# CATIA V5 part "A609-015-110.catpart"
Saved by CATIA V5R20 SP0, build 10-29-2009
Part number: A609-015-110
Source: Unknown
Property "ARTICLENO": "A609-015-110"
Property "B": "12.500"
Property "BOMINFO": "A609-015-110"
Property "CODE": "A609-015-110"
Property "D": "18.000"
Property "D1": "11.000"
Property "FORM": "A"
Property "L": "110.000"
Property "L1": "25.000"
Property "L2": "60.000"
Property "LINA": "A609-015-110"
Property "NB": "A609-015-110"
Property "NBSYN": "$CODE."
Property "NN": "A609"
Property "NT": "VDI 3357 E-Type Wear Plates, self-lubricating"
Property "S": "15.000"
Property "SUPPLIER": "CF"
Property "T": "10.500"
Property "W": "25.000"
Bounding box of the stored display mesh (mm): x 0 to 110, y 0 to 15, z 0 to 25
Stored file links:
  C:\Users\Utente\Desktop\3D files A609\A609-015-110.catpart
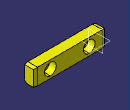
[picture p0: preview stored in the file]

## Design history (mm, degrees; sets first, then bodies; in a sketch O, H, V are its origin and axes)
Body1 "Geometry.1" (main body)
  Solid1 "A609-015-110.catpart": solid without history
